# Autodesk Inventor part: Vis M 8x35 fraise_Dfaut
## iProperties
Created: 2006-03
Part Number: Vis M 8x35 fraise_Dfaut
Document SubType Name: Modeling
Designer: Flavien MARTY
Author: Flavien MARTY
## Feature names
1. Base1
